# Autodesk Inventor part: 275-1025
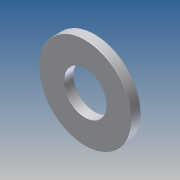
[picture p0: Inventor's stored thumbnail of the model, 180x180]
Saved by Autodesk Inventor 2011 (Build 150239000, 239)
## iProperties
Company: Autodesk Inc.
Created: 2010-06
Part Number: 275-1025
Document SubType Name: Modeling
Designer: Autodesk Inc.
Density: 1 g/cm^3
Catalog Web Link: http://www.vexrobotics.com/washers.html
Vendor: Innovation First, Inc.
Author: Autodesk Inc.
Title: VEX Robotics Kit of Parts
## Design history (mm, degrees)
sketch "Sketch1"
  geometry: C1 r 4.763 at (0, 0); 1 further point
  constraints: 1 centre point, 1 coincident
  dimensions: "d0" = 9.525 diameter of C1
extrude "Extrusion1" new body sketch "Sketch1" distance "d1" = 1.016; taper "d2" = 0 deg
sketch "Sketch2"
  geometry: C1 r 4.763 at (0, 0) reference
hole "Hole1" sketch "Sketch2" at (0, 0) diameter "d3" = 4.3942; stored, may be unused: countersink angle "d7" = 82 deg, drill point angle "d9" = 118 deg; dims "d4" = 19.05, "d5" = 9.525, "d6" = 6.35, "d8" = 25.4
fillet "Fillet1" dims "d10" = 0.0508
body "Solid1"
